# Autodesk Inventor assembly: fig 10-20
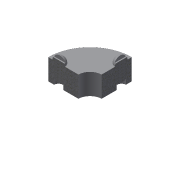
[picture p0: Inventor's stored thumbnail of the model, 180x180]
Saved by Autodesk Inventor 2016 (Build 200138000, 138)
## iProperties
Shininess: 64.0
Angle Display Precision: 2
Document Length Units: 11269
Document Angle Units: 11279
Document Time Units: 11290
Document Mass Units: 11283
Document Length Units Precision: 3
Document Angle Units Precision: 2
Created: 2002-02
Part Number: fig 10-20
Document SubType Name: Assembly
Designer: ***
Density: 0.0
Volumn: 0.0
Area: 0.0
PropertySet Name: Model Information
Control State: 0
Master: False
Checked Out: False
Author: ***
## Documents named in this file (3)
- D:\KAVITA\Autodesk Inventor_ 2016 Project_Kavita\Inventor_Part Files\Inventor_2016_Part\c10_Inv_2016\c10_inv_2016_prt\fig 10-20.iam
- D:\KAVITA\Autodesk Inventor_ 2016 Project_Kavita\Inventor_Part Files\Inventor_2016_Part\c10_Inv_2016\c10_inv_2016_prt\Screw.ipt
- D:\KAVITA\Autodesk Inventor_ 2016 Project_Kavita\Inventor_Part Files\Inventor_2016_Part\c10_Inv_2016\c10_inv_2016_prt\test.ipt
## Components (6 placed, 2 different names)
1. test:1 — Insert:1, Insert:2
2. test:2 — Insert:1
3. Screw:1 — Angle:1, Insert:2
4. Screw:11
5. Screw:12
6. Screw:13
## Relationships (3: Insert 2, Angle 1)
- Insert:1: test:1 ↔ test:2
- Angle:1: Screw:1
- Insert:2: test:1 ↔ Screw:1
